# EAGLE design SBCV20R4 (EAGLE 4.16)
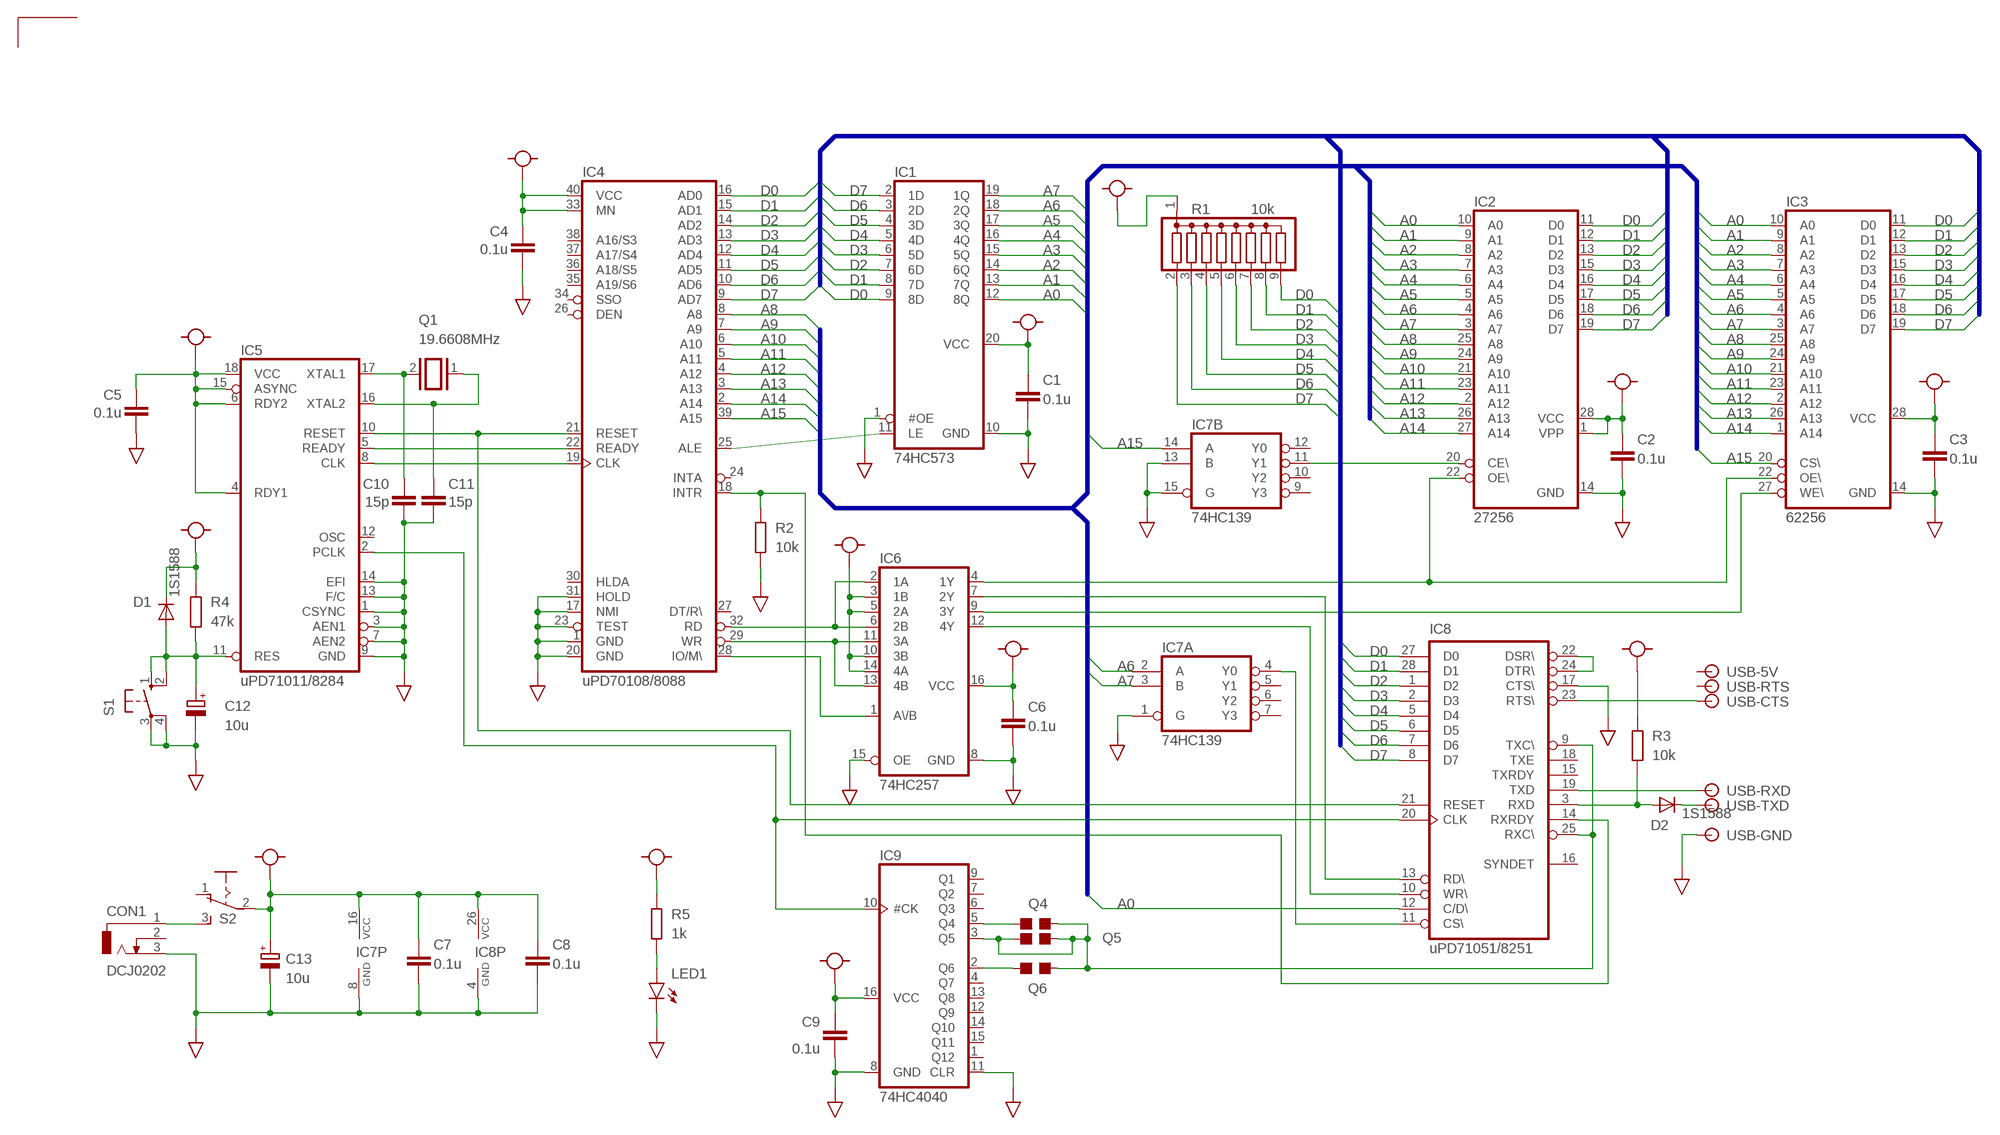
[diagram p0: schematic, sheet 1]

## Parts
C1  0.1u  C-CERAMIC  [C025-025X050]
C2  0.1u  C-CERAMIC  [C025-025X050]
C3  0.1u  C-CERAMIC  [C025-025X050]
C4  0.1u  C-CERAMIC  [C025-025X050]
C5  0.1u  C-CERAMIC  [C025-025X050]
C6  0.1u  C-CERAMIC  [C025-025X050]
C7  0.1u  C-CERAMIC  [C025-025X050]
C8  0.1u  C-CERAMIC  [C025-025X050]
C9  0.1u  C-CERAMIC  [C025-025X050]
C10  15p  C-CERAMIC  [C025-025X050]
C11  15p  C-CERAMIC  [C025-025X050]
C12  10u  C-TANTALUM  [C4518]
C13  10u  C-TANTALUM  [C4518]
CON1  DCJ0202  [DCJ0202]
D1  1S1588  [DO41-10]
D2  1S1588  [DO41-10]
IC1  74HC573  [DIL20]
IC2  27256  27256P  [DIL28]
IC3  62256  62256P  [DIL28]
IC4  uPD70108/8088  8088  [DIL40]
IC5  uPD71011/8284  8284  [DIL18]
IC6  74HC257  74257  [DIL16]
IC7  74HC139  74139  [DIL16]
IC8  uPD71051/8251  8251  [DIL28]
IC9  74HC4040  4040P  [DIL16]
LED1  LED3MM  [LED3MM]
Q1  19.6608MHz  XTAL/S  [QS]
Q4  SOLPAD  [SOLPAD]
Q5  SOLPAD  [SOLPAD]
Q6  SOLPAD  [SOLPAD]
R1  10k  G08R  [SIL9]
R2  10k  R1/8W  [0207/10]
R3  10k  R1/8W  [0207/10]
R4  47k  R1/8W  [0207/10]
R5  1k  R1/8W  [0207/10]
S1  SW-TACT  [B3F-10XX]
S2  255SB  [255SB]
USB-  TTL-232R-5V  [TTL-232R-5V]

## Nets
A0: IC1.12(8Q) IC2.10(A0) IC3.10(A0) IC8.12(C/D\)
A1: IC1.13(7Q) IC2.9(A1) IC3.9(A1)
A2: IC1.14(6Q) IC2.8(A2) IC3.8(A2)
A3: IC1.15(5Q) IC2.7(A3) IC3.7(A3)
A4: IC1.16(4Q) IC2.6(A4) IC3.6(A4)
A5: IC1.17(3Q) IC2.5(A5) IC3.5(A5)
A6: IC1.18(2Q) IC2.4(A6) IC3.4(A6) IC7.2(A:A)
A7: IC1.19(1Q) IC2.3(A7) IC3.3(A7) IC7.3(A:B)
A8: IC2.25(A8) IC3.25(A8) IC4.8(A8)
A9: IC2.24(A9) IC3.24(A9) IC4.7(A9)
A10: IC2.21(A10) IC3.21(A10) IC4.6(A10)
A11: IC2.23(A11) IC3.23(A11) IC4.5(A11)
A12: IC2.2(A12) IC3.2(A12) IC4.4(A12)
A13: IC2.26(A13) IC3.26(A13) IC4.3(A13)
A14: IC2.27(A14) IC3.1(A14) IC4.2(A14)
A15: IC3.20(CS\) IC4.39(A15) IC7.14(B:A)
ALE: IC1.11(LE) IC4.25(ALE)
CLK: IC8.9(TXC\) IC8.25(RXC\) IC9.3(Q5) Q4.2 Q5.1 Q5.2 Q6.2
CS8251: IC7.4(A:Y0) IC8.11(CS\)
D0: IC1.9(8D) IC2.11(D0) IC3.11(D0) IC4.16(AD0) IC8.27(D0) R1.9
D1: IC1.8(7D) IC2.12(D1) IC3.12(D1) IC4.15(AD1) IC8.28(D1) R1.8
D2: IC1.7(6D) IC2.13(D2) IC3.13(D2) IC4.14(AD2) IC8.1(D2) R1.7
D3: IC1.6(5D) IC2.15(D3) IC3.15(D3) IC4.13(AD3) IC8.2(D3) R1.6
D4: IC1.5(4D) IC2.16(D4) IC3.16(D4) IC4.12(AD4) IC8.5(D4) R1.5
D5: IC1.4(3D) IC2.17(D5) IC3.17(D5) IC4.11(AD5) IC8.6(D5) R1.4
D6: IC1.3(2D) IC2.18(D6) IC3.18(D6) IC4.10(AD6) IC8.7(D6) R1.3
D7: IC1.2(1D) IC2.19(D7) IC3.19(D7) IC4.9(AD7) IC8.8(D7) R1.2
GND: C1.2 C2.2 C3.2 C4.2 C5.2 C6.2 C7.2 C8.2 C9.2 C10.2 C11.2 C12.- C13.- CON1.3 IC1.1(#OE) IC1.10(GND) IC2.14(GND) IC3.14(GND) IC4.1(GND) IC4.17(NMI) IC4.20(GND) IC4.23(TEST) IC4.31(HOLD) IC5.1(CSYNC) IC5.3(AEN1) IC5.7(AEN2) IC5.9(GND) IC5.13(F/C) IC5.14(EFI) IC6.8(GND) IC6.15(OE) IC7.1(A:G) IC7.8(P:GND) IC7.13(B:B) IC7.15(B:G) IC8.4(GND) IC8.17(CTS\) IC9.8(GND) IC9.11(CLR) LED1.K(C) R2.2 S1.3(P) S1.4(P1) USB-.1
IOM: IC4.28(IO/M\) IC6.1(A\/B)
IOR: IC6.7(2Y) IC8.13(RD\)
IOW: IC6.12(4Y) IC8.10(WR\)
MEMR: IC2.22(OE\) IC3.22(OE\) IC6.4(1Y)
MEMW: IC3.27(WE\) IC6.9(3Y)
N$1: CON1.1 S2.3(S)
N$2: IC9.5(Q4) Q4.1
N$3: C10.1 IC5.17(XTAL1) Q1.2
N$4: D2.A IC8.3(RXD) R3.1
N$5: D2.C USB-.4
N$7: IC9.2(Q6) Q6.1
N$14: C11.1 IC5.16(XTAL2) Q1.1
N$15: IC4.32(RD) IC6.2(1A) IC6.6(2B)
N$16: IC4.29(WR) IC6.11(3A) IC6.13(4B)
N$19: IC4.22(READY) IC5.5(READY)
N$36: LED1.A R5.2
N$38: IC4.19(CLK) IC5.8(CLK)
N$40: IC8.22(DSR\) IC8.24(DTR\)
N$41: IC2.20(CE\) IC7.11(B:Y1)
N$48: IC4.18(INTR) IC8.14(RXRDY) R2.1
PCLK: IC5.2(PCLK) IC8.20(CLK) IC9.10(#CK)
RESET: IC4.21(RESET) IC5.10(RESET) IC8.21(RESET)
RESIN: C12.+ D1.A IC5.11(RES) R4.2 S1.1(S) S1.2(S1)
RTS: IC8.23(RTS\) USB-.2
TXD: IC8.19(TXD) USB-.5
VCC: C1.1 C2.1 C3.1 C4.1 C5.1 C6.1 C7.1 C8.1 C9.1 C13.+ D1.C IC1.20(VCC) IC2.1(VPP) IC2.28(VCC) IC3.28(VCC) IC4.33(MN) IC4.40(VCC) IC5.4(RDY1) IC5.6(RDY2) IC5.15(ASYNC) IC5.18(VCC) IC6.3(1B) IC6.5(2A) IC6.10(3B) IC6.14(4A) IC6.16(VCC) IC7.16(P:VCC) IC8.26(VCC) IC9.16(VCC) R1.1 R3.2 R4.1 R5.1 S2.2(P)
Unconnected: CON1.2 IC4.24(INTA) IC4.26(DEN) IC4.27(DT/R\) IC4.30(HLDA) IC4.34(SSO) IC4.35(A19/S6) IC4.36(A18/S5) IC4.37(A17/S4) IC4.38(A16/S3) IC5.12(OSC) IC7.5(A:Y1) IC7.6(A:Y2) IC7.7(A:Y3) IC7.9(B:Y3) IC7.10(B:Y2) IC7.12(B:Y0) IC8.15(TXRDY) IC8.16(SYNDET) IC8.18(TXE) IC9.1(Q12) IC9.4(Q7) IC9.6(Q3) IC9.7(Q2) IC9.9(Q1) IC9.12(Q9) IC9.13(Q8) IC9.14(Q10) IC9.15(Q11) S2.1(O) USB-.3 USB-.6

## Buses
D[0..7]
A[0..15]

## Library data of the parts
C1-C11 = olimex-devices:C-CERAMIC: Ceramic Conenser
C12 C13 = olimex-devices:C-TANTALUM: Tantalum Condenser
CON1 = olimex-devices:DCJ0202: DC POWER JACK Source: DCJ0202.pdf
D1 D2 = olimex-devices:1S1588: Small Signal Diode
IC1 = olimex-devices:74HC573
IC2 = olimex-devices:27256P
IC3 = olimex-devices:62256P
IC4 = olimex-devices:8088
IC5 = olimex-devices:8284
IC6 = olimex-devices:74257
IC7 = olimex-devices:74139
IC8 = olimex-devices:8251: Intel Programmable Comunication Interface
IC9 = olimex-devices:4040P
LED1 = olimex-devices:LED3MM: LED
Q1 = olimex-devices:XTAL/S: X'tal Oscirator
Q4-Q6 = olimex-devices:SOLPAD
R1 = olimex-devices:G08R: SIL RESISTOR
R2-R5 = olimex-devices:R1/8W: Carbon Resistor
S1 = olimex-devices:SW-TACT: Tact Switch (Small)
S2 = olimex-devices:255SB: SLIDING SWITCH distributor Buerklin, 11G810
USB- = olimex-devices:TTL-232R-5V

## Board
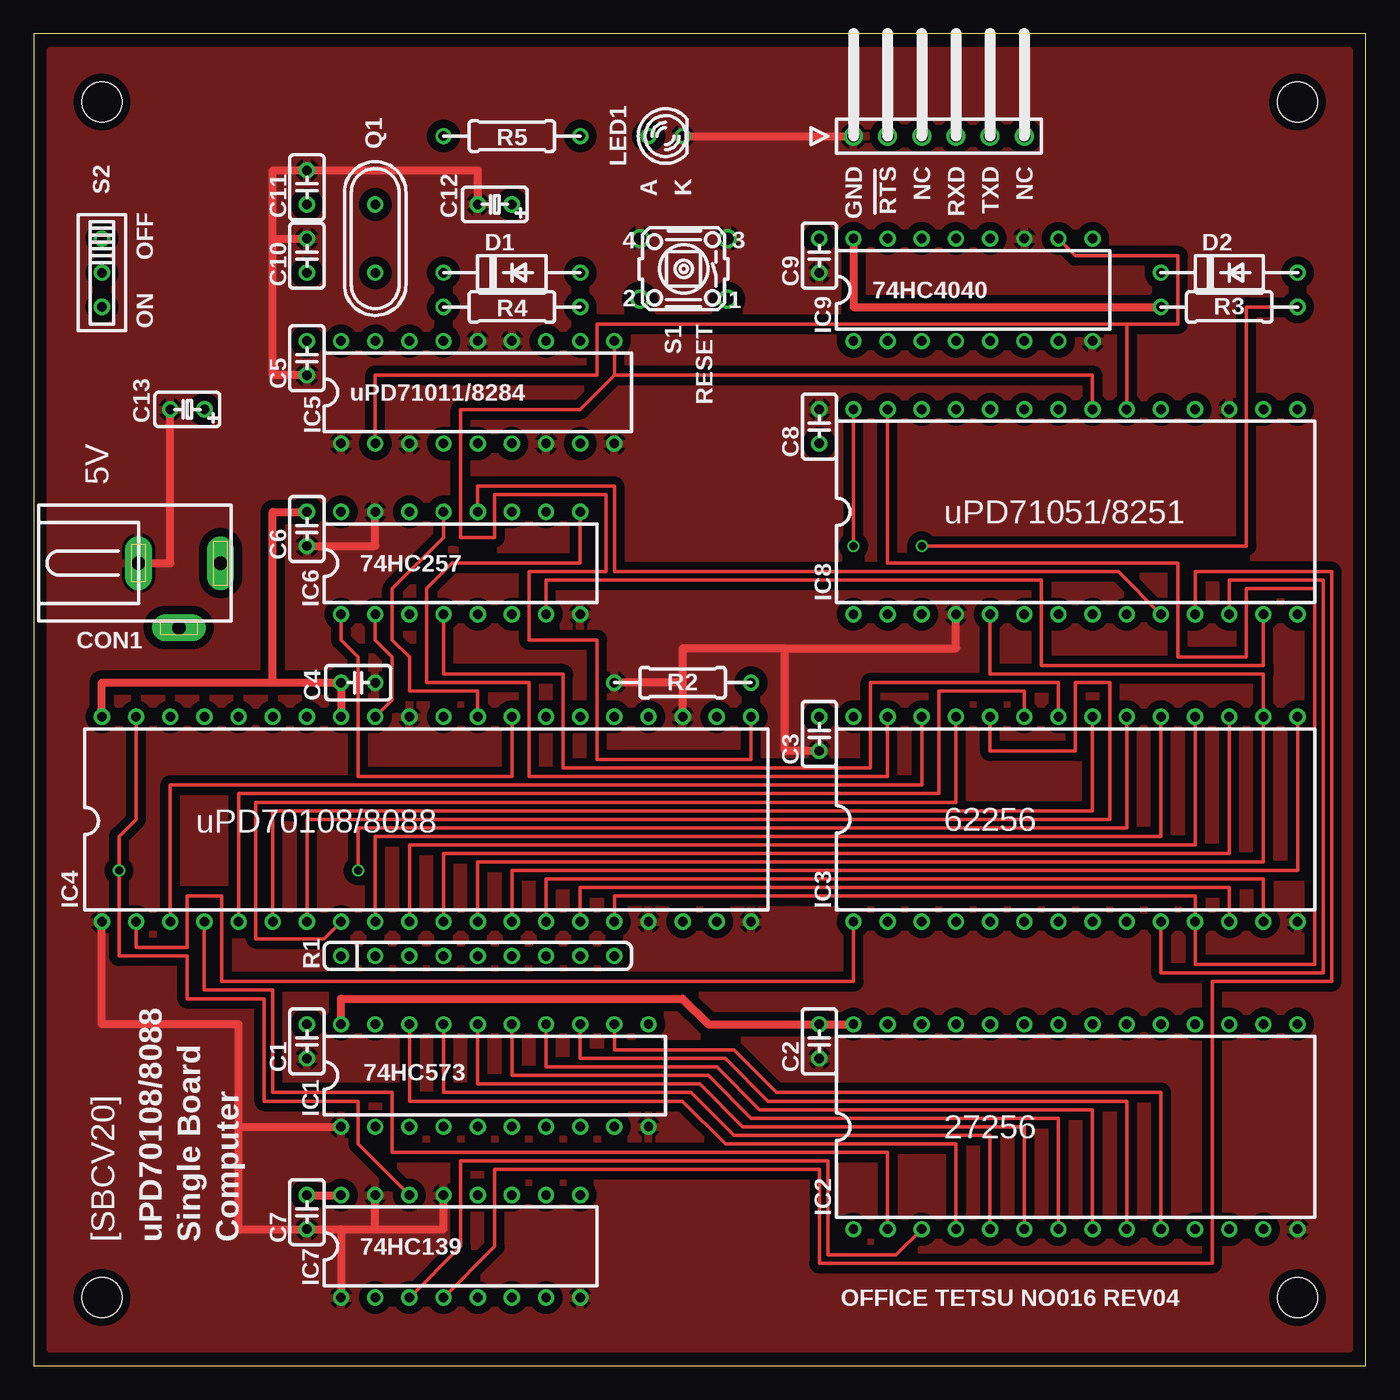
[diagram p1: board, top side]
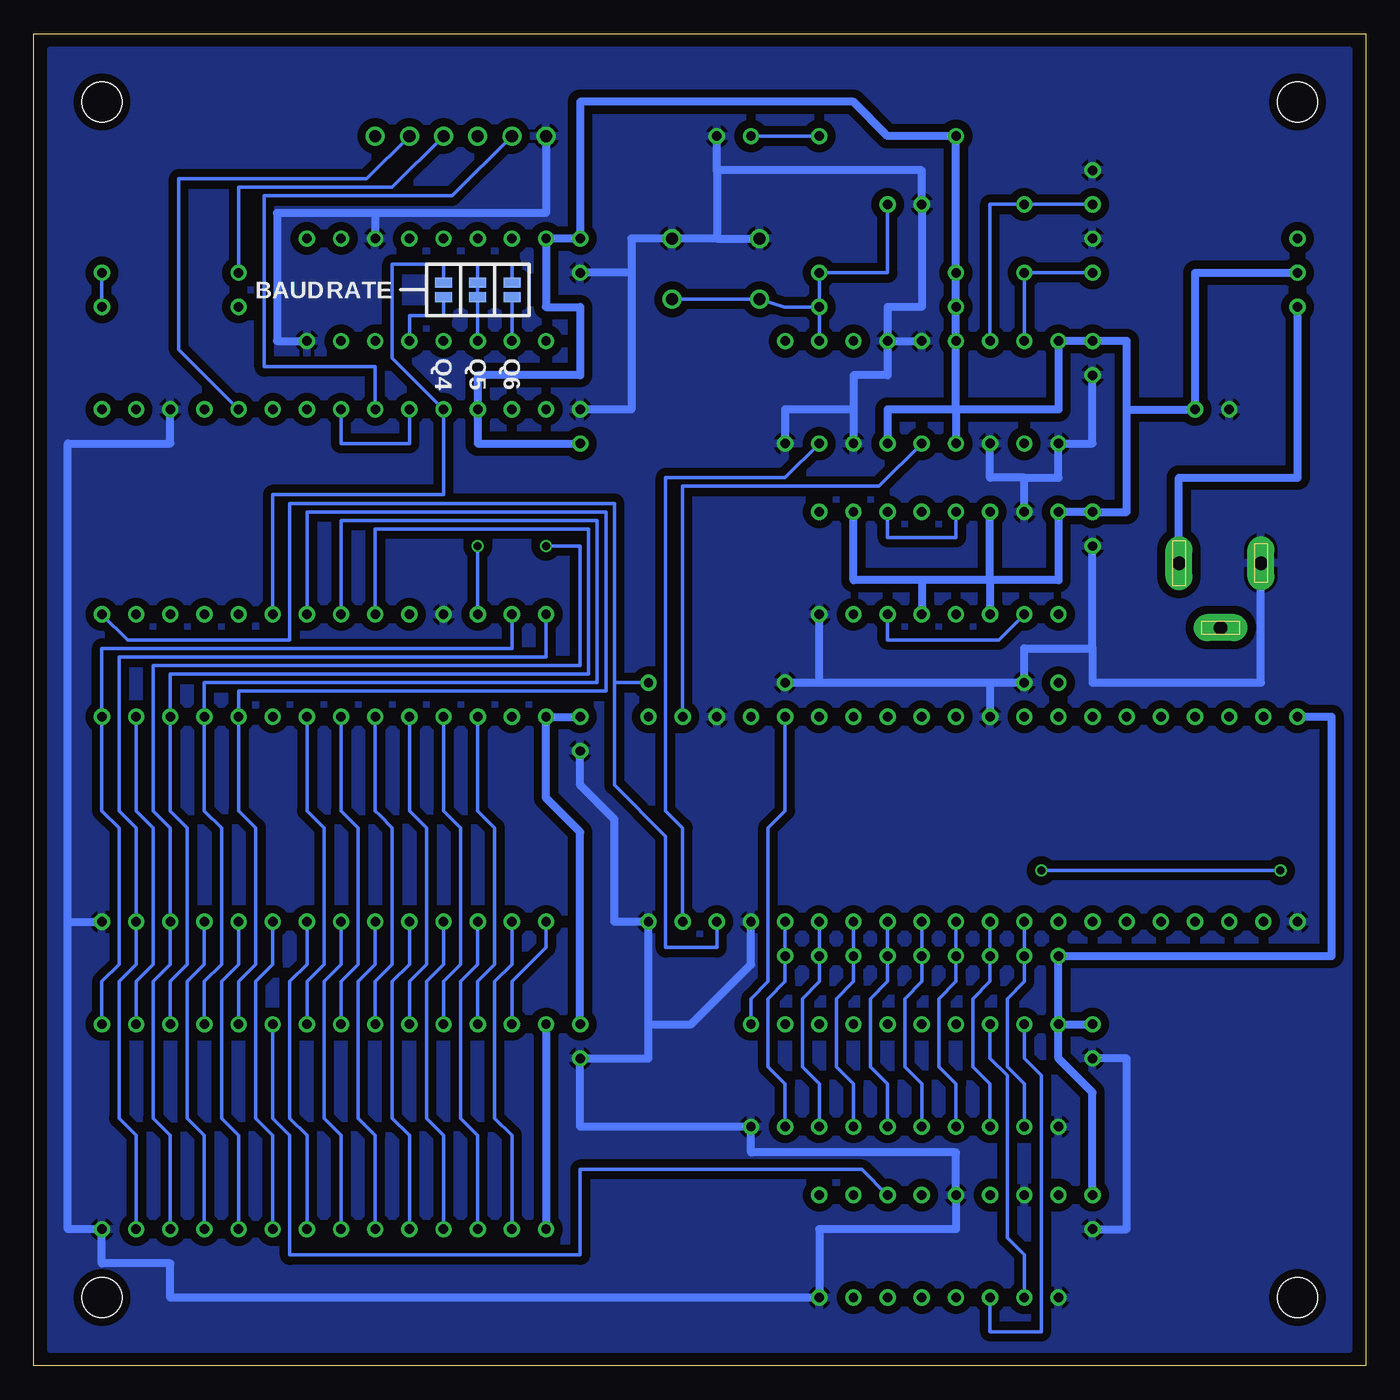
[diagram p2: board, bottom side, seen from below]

Size 99.06 x 99.06 mm. Coordinates in mm from the lower left corner, seen from the top.
Outline: 99.06,0 99.06,99.06 0,99.06 0,0 99.06,0
Copper layers (1*16): Top 0.035mm / dielectric 1.5mm / Bottom 0.035mm
Design rules "OfficeTETSUstandard": minimum track width 6mil, minimum drill 12mil, track to track 6mil, track to pad 6mil, pad to pad 6mil, via to via 6mil, smd to smd 0mil, copper to edge 10mil, drill to drill 10mil, minimum pad ring 10mil, minimum via ring 6mil, stop-mask expansion 2mil, vias tented up to drill 25mil, thermal gap 10mil
Holes 3 mm at 93.98,93.98 5.08,93.98 93.98,5.08 5.08,5.08

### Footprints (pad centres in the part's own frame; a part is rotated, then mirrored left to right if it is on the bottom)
C025-025X050 = drill 0.7 round: 1 -1.27,0; 2 1.27,0
C4518 = drill 0.7 round: + -1.27,0; - 1.27,0
DCJ0202 = drill 1 pad 2 long: 1 0,3.1; 2 4.8,0; 3 0,-3
DO41-10 = drill 0.7 round: A 5.08,0; C -5.08,0
DIL20 = drill 0.7 round: 1 -11.43,-3.81; 2 -8.89,-3.81; 3 -6.35,-3.81; 4 -3.81,-3.81; 5 -1.27,-3.81; 6 1.27,-3.81; 7 3.81,-3.81; 8 6.35,-3.81; 9 8.89,-3.81; 10 11.43,-3.81; 11 11.43,3.81; 12 8.89,3.81; 13 6.35,3.81; 14 3.81,3.81; 15 1.27,3.81; 16 -1.27,3.81; 17 -3.81,3.81; 18 -6.35,3.81; 19 -8.89,3.81; 20 -11.43,3.81
DIL28 = drill 0.7 round: 1 -16.51,-7.62; 2 -13.97,-7.62; 3 -11.43,-7.62; 4 -8.89,-7.62; 5 -6.35,-7.62; 6 -3.81,-7.62; 7 -1.27,-7.62; 8 1.27,-7.62; 9 3.81,-7.62; 10 6.35,-7.62; 11 8.89,-7.62; 12 11.43,-7.62; 13 13.97,-7.62; 14 16.51,-7.62; 15 16.51,7.62; 16 13.97,7.62; 17 11.43,7.62; 18 8.89,7.62; 19 6.35,7.62; 20 3.81,7.62; 21 1.27,7.62; 22 -1.27,7.62; 23 -3.81,7.62; 24 -6.35,7.62; 25 -8.89,7.62; 26 -11.43,7.62; 27 -13.97,7.62; 28 -16.51,7.62
DIL40 = drill 0.7 round: 1 -24.13,-7.62; 2 -21.59,-7.62; 3 -19.05,-7.62; 4 -16.51,-7.62; 5 -13.97,-7.62; 6 -11.43,-7.62; 7 -8.89,-7.62; 8 -6.35,-7.62; 9 -3.81,-7.62; 10 -1.27,-7.62; 11 1.27,-7.62; 12 3.81,-7.62; 13 6.35,-7.62; 14 8.89,-7.62; 15 11.43,-7.62; 16 13.97,-7.62; 17 16.51,-7.62; 18 19.05,-7.62; 19 21.59,-7.62; 20 24.13,-7.62; 21 24.13,7.62; 22 21.59,7.62; 23 19.05,7.62; 24 16.51,7.62; 25 13.97,7.62; 26 11.43,7.62; 27 8.89,7.62; 28 6.35,7.62; 29 3.81,7.62; 30 1.27,7.62; 31 -1.27,7.62; 32 -3.81,7.62; 33 -6.35,7.62; 34 -8.89,7.62; 35 -11.43,7.62; 36 -13.97,7.62; 37 -16.51,7.62; 38 -19.05,7.62; 39 -21.59,7.62; 40 -24.13,7.62
DIL18 = drill 0.7 round: 1 -10.16,-3.81; 2 -7.62,-3.81; 3 -5.08,-3.81; 4 -2.54,-3.81; 5 0,-3.81; 6 2.54,-3.81; 7 5.08,-3.81; 8 7.62,-3.81; 9 10.16,-3.81; 10 10.16,3.81; 11 7.62,3.81; 12 5.08,3.81; 13 2.54,3.81; 14 0,3.81; 15 -2.54,3.81; 16 -5.08,3.81; 17 -7.62,3.81; 18 -10.16,3.81
DIL16 = drill 0.7 round: 1 -8.89,-3.81; 2 -6.35,-3.81; 3 -3.81,-3.81; 4 -1.27,-3.81; 5 1.27,-3.81; 6 3.81,-3.81; 7 6.35,-3.81; 8 8.89,-3.81; 9 8.89,3.81; 10 6.35,3.81; 11 3.81,3.81; 12 1.27,3.81; 13 -1.27,3.81; 14 -3.81,3.81; 15 -6.35,3.81; 16 -8.89,3.81
LED3MM = drill 0.7 round: A -1.27,0; K 1.27,0
QS = drill 0.7 round: 1 -2.54,0; 2 2.54,0
SOLPAD = smd 0.736 x 1.27: 1 -0.54,0; 2 0.54,0
SIL9 = drill 0.7 round: 1 -10.16,0; 2 -7.62,0; 3 -5.08,0; 4 -2.54,0; 5 0,0; 6 2.54,0; 7 5.08,0; 8 7.62,0; 9 10.16,0
0207/10 = drill 0.7 round: 1 -5.08,0; 2 5.08,0
B3F-10XX = drill 0.9 round: 1 -3.251,2.261; 2 3.251,2.261; 3 -3.251,-2.261; 4 3.251,-2.261
255SB = drill 0.7 round: 1 -2.54,0; 2 0,0; 3 2.54,0
TTL-232R-5V = drill 0.9 round: 1 -6.35,0; 2 -3.81,0; 3 -1.27,0; 4 1.27,0; 5 3.81,0; 6 6.35,0

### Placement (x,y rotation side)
C1  20.32,24.13 270 top
C2  58.42,24.13 270 top
C3  58.42,46.99 270 top
C4  24.13,50.8 0 top
C5  20.32,74.93 270 top
C6  20.32,62.23 270 top
C7  20.32,11.43 270 top
C8  58.42,69.85 90 top
C9  58.42,82.55 270 top
C10  20.32,82.55 90 top
C11  20.32,87.63 90 top
C12  34.29,86.36 180 top
C13  11.43,71.12 180 top
CON1  10.79,59.69 270 top
D1  35.56,81.28 0 top
D2  88.9,81.28 0 top
IC1  34.29,21.59 0 top
IC2  77.47,17.78 0 top
IC3  77.47,40.64 0 top
IC4  29.21,40.64 0 top
IC5  33.02,72.39 0 top
IC6  31.75,59.69 0 top
IC7  31.75,8.89 0 top
IC8  77.47,63.5 0 top
IC9  69.85,80.01 0 top
LED1  46.99,91.44 0 top
Q1  25.4,83.82 270 top
Q4  68.58,80.01 90 bottom
Q5  66.04,80.01 90 bottom
Q6  63.5,80.01 90 bottom
R1  33.02,30.48 0 top
R2  48.26,50.8 180 top
R3  88.9,78.74 180 top
R4  35.56,78.74 0 top
R5  35.56,91.44 0 top
S1  48.33,81.57 180 top
S2  5.08,81.28 270 top
USB-  67.31,91.44 0 top

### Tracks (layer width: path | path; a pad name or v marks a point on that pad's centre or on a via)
A0
  Top 0.254: IC1.12 43.18,23.5 52.07,23.5 55.24,20.32 83.82,20.32 IC2.10 | IC8.12 88.9,58.42 95.89,58.42 95.89,29.21 83.82,29.21 IC3.10
  Bottom 0.254: IC3.10 83.82,29.84 85.09,28.57 85.09,18.41 83.82,17.14 IC2.10
A1
  Top 0.254: IC1.13 40.64,22.86 51.44,22.86 54.61,19.68 81.28,19.68 IC2.9
  Bottom 0.254: IC3.9 81.28,29.84 82.55,28.57 82.55,18.41 81.28,17.14 IC2.9
A2
  Top 0.254: IC1.14 38.1,22.23 50.8,22.23 53.98,19.05 78.74,19.05 IC2.8
  Bottom 0.254: IC3.8 78.74,29.84 80.01,28.57 80.01,18.41 78.74,17.14 IC2.8
A3
  Top 0.254: IC1.15 35.56,21.59 50.16,21.59 53.34,18.41 76.2,18.41 IC2.7
  Bottom 0.254: IC3.7 76.2,29.84 77.47,28.57 77.47,18.41 76.2,17.14 IC2.7
A4
  Top 0.254: IC1.16 33.02,20.95 49.53,20.95 52.7,17.78 73.66,17.78 IC2.6
  Bottom 0.254: IC3.6 73.66,29.84 74.93,28.57 74.93,18.41 73.66,17.14 IC2.6
A5
  Top 0.254: IC1.17 30.48,20.32 48.9,20.32 52.07,17.14 71.12,17.14 IC2.5
  Bottom 0.254: IC3.5 71.12,29.84 72.39,28.57 72.39,18.41 71.12,17.14 IC2.5
A6
  Top 0.254: IC1.18 27.94,19.68 48.26,19.68 51.44,16.51 68.58,16.51 IC2.4
  Bottom 0.254: IC1.18 27.94,22.86 26.67,21.59 26.67,9.53 25.4,8.26 IC7.2 | IC3.4 68.58,29.84 69.85,28.57 69.85,18.41 68.58,17.14 IC2.4
A7
  Top 0.254: IC7.3 31.75,8.89 31.75,15.24 59.05,15.24 59.05,8.26 64.14,8.26 IC2.3
  Bottom 0.254: IC1.19 25.4,22.86 24.13,21.59 24.13,2.54 27.94,2.54 IC7.3 | IC3.3 66.04,29.84 67.31,28.57 67.31,18.41 66.04,17.14 IC2.3
A8
  Top 0.254: IC3.25 68.58,41.91 16.51,41.91 16.51,31.75 21.59,31.75 IC4.8
  Bottom 0.254: IC3.25 68.58,41.27 67.31,40.01 67.31,29.84 68.58,28.57 IC2.25
A9
  Top 0.254: IC4.7 20.32,40.64 80.01,40.64 80.01,50.8 77.47,50.8 77.47,45.72 71.12,45.72 IC3.24
  Bottom 0.254: IC3.24 71.12,41.27 69.85,40.01 69.85,29.84 71.12,28.57 IC2.24
A10
  Top 0.254: IC4.6 17.78,41.27 78.74,41.27 IC3.21
  Bottom 0.254: IC3.21 78.74,41.27 77.47,40.01 77.47,29.84 78.74,28.57 IC2.21
A11
  Top 0.254: IC3.23 73.66,50.16 67.31,50.16 67.31,42.55 15.24,42.55 IC4.5
  Bottom 0.254: IC3.23 73.66,41.27 73.34,40.96 72.39,40.01 72.39,29.84 73.66,28.57 IC2.23
A12
  Top 0.254: IC4.4 12.7,27.94 17.78,27.94 17.78,20.32 26.67,20.32 26.67,15.88 63.5,15.88 IC2.2
  Bottom 0.254: IC2.2 63.5,17.14 64.77,18.41 64.77,28.57 63.5,29.84 IC3.2
A13
  Top 0.254: IC4.3 10.16,43.18 66.04,43.18 IC3.26
  Bottom 0.254: IC3.26 66.04,41.27 64.77,40.01 64.77,29.84 66.04,28.57 IC2.26
A14
  Top 0.254: IC3.1 60.96,28.57 13.97,28.57 13.97,34.92 11.43,34.92 11.43,31.11 7.62,31.11 IC4.2
  Bottom 0.254: IC2.27 63.5,28.57 60.96,31.11 IC3.1
A15  (via drill 0.6)
  Top 0.254: IC7.14 24.13,16.51 24.13,19.68 17.14,19.68 17.14,27.3 11.43,27.3 11.43,30.48 6.35,30.48 v6.35,36.83 6.35,39.37 7.62,40.64 IC4.39 | v24.13,36.83 24.13,40.01 81.28,40.01 IC3.20
  Bottom 0.254: v6.35,36.83 v24.13,36.83
ALE
  Bottom 0.254: IC1.11 45.72,27.3 44.45,28.57 44.45,40.01 43.18,41.27 IC4.25
CLK
  Bottom 0.254: 66.04,79.38 IC9.3 | Q6.2 63.5,81.92 66.04,81.92 | 66.04,81.92 Q5.2 66.04,79.38 | 66.04,79.38 Q5.1 | 68.58,81.92 72.39,81.92 72.39,74.93 IC8.25 68.58,64.77 81.28,64.77 IC8.9 | 68.58,81.92 66.04,81.92 | 68.58,81.92 Q4.2
CS8251
  Top 0.254: IC7.4 34.29,8.89 34.29,14.61 58.42,14.61 58.42,7.62 87.63,7.62 87.63,28.57 96.52,28.57 96.52,59.05 86.36,59.05 IC8.11
D0
  Top 0.254: IC4.16 43.18,34.92 86.36,34.92 IC3.11 86.36,29.84 95.25,29.84 95.25,57.78 90.17,57.78 90.17,52.7 85.09,52.7 85.09,59.69 63.5,59.69 IC8.27
  Bottom 0.254: IC1.9 43.18,20.95 44.45,22.23 44.45,27.3 43.18,28.57 R1.9 IC4.16 | IC3.11 86.36,29.84 87.63,28.57 87.63,18.41 86.36,17.14 IC2.11
D1  (via drill 0.6)
  Top 0.254: IC4.15 40.64,35.56 88.9,35.56 IC3.12 | v60.96,60.96 IC8.28
  Bottom 0.254: IC1.8 40.64,20.95 41.91,22.23 41.91,27.3 40.64,28.57 R1.8 IC4.15 | v60.96,60.96 58.42,60.96 58.42,52.07 90.17,52.07 90.17,41.27 88.9,40.01 IC3.12 88.9,29.84 90.17,28.57 90.17,18.41 88.9,17.14 IC2.12
D2
  Top 0.254: IC4.14 38.1,36.2 91.44,36.2 IC3.13
  Bottom 0.254: IC8.1 60.96,52.7 92.71,52.7 92.71,41.27 91.44,40.01 IC3.13 91.44,29.84 92.71,28.57 92.71,18.41 91.44,17.14 IC2.13 | IC1.7 38.1,20.95 39.37,22.23 39.37,27.3 38.1,28.57 R1.7 IC4.14
D3
  Top 0.254: IC4.13 35.56,36.83 93.98,36.83 IC3.15
  Bottom 0.254: IC8.2 63.5,53.34 93.98,53.34 IC3.15 93.98,41.27 92.71,40.01 92.71,29.84 93.98,28.57 IC2.15 | IC1.6 35.56,20.95 36.83,22.23 36.83,27.3 35.56,28.57 R1.6 IC4.13
D4
  Top 0.254: IC4.12 33.02,37.47 91.44,37.47 IC3.16 91.44,51.44 71.12,51.44 IC8.5
  Bottom 0.254: IC1.5 33.02,20.95 34.29,22.23 34.29,27.3 33.02,28.57 R1.5 IC4.12 | IC3.16 91.44,41.27 90.17,40.01 90.17,29.84 91.44,28.57 IC2.16
D5
  Top 0.254: IC4.11 30.48,38.1 88.9,38.1 IC3.17
  Bottom 0.254: IC8.6 73.66,62.23 57.78,62.23 57.78,51.44 88.9,51.44 IC3.17 88.9,41.27 87.63,40.01 87.63,29.84 88.9,28.57 IC2.17 | IC1.4 30.48,20.95 31.75,22.23 31.75,27.3 30.48,28.57 R1.4 IC4.11
D6
  Top 0.254: IC4.10 27.94,38.73 86.36,38.73 IC3.18
  Bottom 0.254: IC8.7 76.2,62.87 57.15,62.87 57.15,50.8 86.36,50.8 IC3.18 86.36,41.27 85.09,40.01 85.09,29.84 86.36,28.57 IC2.18 | IC1.3 27.94,20.95 29.21,22.23 29.21,27.3 27.94,28.57 R1.3 IC4.10
D7
  Top 0.254: IC4.9 25.4,39.37 83.82,39.37 IC3.19
  Bottom 0.254: IC8.8 78.74,63.5 56.52,63.5 56.52,50.16 83.82,50.16 IC3.19 83.82,41.27 82.55,40.01 82.55,29.84 83.82,28.57 IC2.19 | IC1.2 25.4,20.95 26.67,22.23 26.67,27.3 25.4,28.57 R1.2 IC4.9
GND
  Top 0.61: 22.86,10.16 IC7.1 | 22.86,10.16 C7.2 15.24,10.16 15.24,17.78 | 25.4,10.16 IC7.15 | 22.86,10.16 25.4,10.16 | IC7.13 30.48,10.16 25.4,10.16 | IC4.1 5.08,25.4 15.24,25.4 15.24,17.78 | 48.26,50.8 IC4.23 | 48.26,50.8 R2.2 | CON1.3 10.16,59.69 C13.- | C6.2 25.4,60.96 IC6.15 | LED1.K USB-.1 | C5.2 17.78,73.66 17.78,83.82 | 17.78,83.82 17.78,88.9 C11.2 33.02,88.9 C12.- | 15.24,17.78 IC1.1 | IC8.4 68.58,53.34 55.88,53.34 | 55.88,53.34 55.88,45.72 C3.2 | 48.26,50.8 48.26,53.34 55.88,53.34 | 17.78,83.82 C10.2
  Bottom 0.61: 53.34,25.4 53.34,22.86 C2.2 58.42,17.78 IC1.10 45.72,15.88 30.48,15.88 IC7.13 30.48,10.16 40.64,10.16 IC7.8 88.9,5.08 88.9,7.62 93.98,7.62 IC2.14 96.52,10.16 96.52,33.02 | 53.34,25.4 IC4.20 55.88,33.02 55.88,40.64 58.42,43.18 C3.2 | IC4.17 45.72,29.84 50.16,25.4 53.34,25.4 | C5.2 20.32,68.58 IC5.1 22.86,66.04 25.4,66.04 | 25.4,66.04 27.94,66.04 IC5.3 | IC6.15 25.4,66.04 | 20.32,53.34 20.32,50.8 7.79,50.8 CON1.3 | 20.32,53.34 C6.2 | 27.94,50.8 IC4.31 | 27.94,50.8 C4.2 25.4,53.34 20.32,53.34 | 48.26,83.83 S1.4 | 48.26,88.9 LED1.K | 48.26,88.9 48.26,83.83 | 48.26,83.83 S1.3 54.61,83.83 54.61,81.28 | 48.26,83.83 48.26,83.82 | IC5.13 35.56,78.74 33.02,78.74 C12.- 33.02,88.9 48.26,88.9 | IC5.13 IC5.14 | 54.61,81.28 C9.2 | USB-.1 60.96,85.72 73.66,85.72 | 73.66,85.72 IC9.11 | IC5.13 35.56,73.66 38.1,73.66 38.1,71.12 | 38.1,71.12 IC5.7 | IC9.8 80.96,76.2 80.96,85.72 73.66,85.72 | 40.64,50.8 IC6.8 | R2.2 40.64,50.8 | 40.64,50.8 27.94,50.8 | C8.2 54.61,71.12 54.61,81.28 | IC5.9 43.18,71.12 38.1,71.12 | C1.2 17.78,22.86 17.78,10.16 C7.2 | 96.52,33.02 IC3.14 | IC8.17 88.9,68.58 96.52,68.58 96.52,33.02
  pour Top (isolate 0.61): 1.27,1.27 1.27,97.79 97.79,97.79 97.79,1.27
  pour Bottom (isolate 0.61): 1.27,1.27 1.27,97.79 97.79,97.79 97.79,1.27
IOM
  Top 0.254: IC4.28 35.56,43.81 24.13,43.81 24.13,52.7 22.86,53.98 IC6.1
IOR
  Top 0.254: IC8.13 91.44,52.07 74.93,52.07 74.93,58.42 38.1,58.42 IC6.7
IOW
  Top 0.254: IC8.10 80.64,59.05 75.56,59.05 | 75.56,59.05 77.47,59.05 | 75.56,59.05 43.18,59.05 43.18,65.41 33.02,65.41 IC6.12
MEMR
  Top 0.254: IC6.4 30.48,51.44 39.37,51.44 39.37,44.45 62.23,44.45 62.23,50.8 76.2,50.8 IC3.22
  Bottom 0.254: IC2.22 76.2,28.57 74.93,29.84 74.93,40.01 76.2,41.27 IC3.22
MEMW
  Top 0.254: IC3.27 63.5,43.81 36.83,43.81 36.83,50.8 29.21,50.8 29.21,57.78 31.11,59.69 40.64,59.69 IC6.9
N$1
  Bottom 0.61: CON1.1 13.89,66.04 5.08,66.04 S2.3
N$2
  Bottom 0.254: Q4.1 68.58,78.11 71.12,78.11 IC9.5
N$3
  Bottom 0.254: IC5.17 Q1.2 C10.1
N$4  (via drill 0.6)
  Top 0.254: v66.04,60.96 90.17,60.96 90.17,78.74 R3.1
  Bottom 0.254: IC8.3 v66.04,60.96 | R3.1 D2.A
N$5
  Bottom 0.254: USB-.4 72.39,87.63 83.82,87.63 D2.C
N$7
  Bottom 0.254: IC9.2 Q6.1
N$14
  Bottom 0.254: IC5.16 27.94,86.36 Q1.1 C11.1
N$15
  Top 0.254: IC4.32 26.67,49.53 26.67,52.7 25.4,53.98 IC6.2
  Bottom 0.254: IC6.2 27.3,53.98 35.56,53.98 IC6.6
N$16
  Top 0.254: IC4.29 33.02,50.16 27.94,50.16 27.94,52.7 26.67,53.98 26.67,57.78 30.48,61.59 IC6.13
  Bottom 0.254: IC6.13 30.48,61.59 35.56,61.59 IC6.11
N$19
  Bottom 0.254: IC4.22 50.8,65.41 36.2,65.41 IC5.5
N$36
  Bottom 0.254: R5.2 LED1.A
N$38
  Bottom 0.254: IC4.19 50.8,40.01 52.07,41.27 52.07,66.04 43.18,66.04 IC5.8
N$40
  Bottom 0.254: IC8.24 71.12,68.58 76.2,68.58 IC8.22
N$41
  Bottom 0.254: IC7.11 37.47,14.61 58.42,14.61 58.42,8.26 80.01,8.26 80.01,17.14 81.28,18.41 IC2.20
N$48
  Bottom 0.254: IC8.14 92.08,53.98 80.01,53.98 80.01,64.14 55.88,64.14 55.88,50.8 | IC4.18 48.26,31.11 52.07,31.11 52.07,39.37 55.88,43.18 55.88,50.8 | 55.88,50.8 R2.1
PCLK
  Top 0.254: IC5.2 25.4,73.66 41.91,73.66 41.91,77.47 81.28,77.47 | 81.28,77.47 IC8.20 | 81.28,77.47 85.09,77.47 85.09,82.55 77.47,82.55 IC9.10
RESET
  Top 0.254: IC8.21 78.74,73.66 43.18,73.66 | 43.18,73.66 IC5.10 | 43.18,73.66 40.64,71.12 31.75,71.12 31.75,61.59 34.29,61.59 34.29,64.77 42.55,64.77 42.55,59.05 36.83,59.05 36.83,53.98 41.91,53.98 41.91,45.09 53.34,45.09 IC4.21
RESIN
  Bottom 0.254: R4.2 43.25,78.74 S1.2 51.44,79.31 | 51.44,79.31 S1.1 | 51.44,79.31 51.44,79.38 | IC5.11 R4.2 | R4.2 D1.A 35.56,81.28 C12.+
RTS
  Bottom 0.254: IC8.23 73.66,74.3 81.92,74.3 81.92,87 67.94,87 USB-.2
TXD
  Bottom 0.254: USB-.5 74.3,88.27 88.27,88.27 88.27,75.56 IC8.19
VCC
  Top 0.61: C7.1 IC7.16 | IC4.33 C4.1 17.78,50.8 | 17.78,50.8 17.78,63.5 C6.1 | IC1.20 22.86,27.3 48.26,27.3 50.16,25.4 C2.1 IC2.28 | IC4.40 5.08,50.8 17.78,50.8 | R3.2 60.96,78.74 IC9.16
  Bottom 0.61: IC1.20 22.86,22.86 20.32,20.32 C7.1 | IC1.20 C1.1 | IC1.20 R1.1 2.54,30.48 2.54,48.26 IC4.40 | C3.1 IC3.28 60.96,42.23 58.42,39.69 C2.1 | C8.1 66.04,68.58 IC8.26 66.04,73.66 58.42,73.66 58.42,78.74 60.96,78.74 IC9.16 C9.1 58.42,93.98 38.1,93.98 35.56,91.44 R5.1 D1.C R4.1 IC5.15 30.48,71.12 | S2.2 12.7,81.28 C13.+ 17.78,71.12 | 17.78,71.12 17.78,63.5 C6.1 IC6.16 22.86,58.42 27.94,58.42 | 17.78,71.12 17.78,76.2 C5.1 IC5.18 22.86,71.12 30.48,71.12 | 30.48,71.12 IC5.4 | IC5.6 35.56,71.12 30.48,71.12 | 27.94,58.42 IC6.14 | 27.94,58.42 IC6.3 | 33.02,58.42 IC6.5 | 27.94,58.42 33.02,58.42 | IC6.10 38.1,58.42 33.02,58.42 | IC2.28 IC2.1

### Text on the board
tPlace: GND | RTS | NC | RXD | TXD | NC | A | K | OFF | ON | RESET | 5V | [SBCV20] | uPD70108/8088 | Single Board | Computer | OFFICE TETSU NO016 REV04
bPlace: RATE | BAUD | Q6 | Q5 | Q4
